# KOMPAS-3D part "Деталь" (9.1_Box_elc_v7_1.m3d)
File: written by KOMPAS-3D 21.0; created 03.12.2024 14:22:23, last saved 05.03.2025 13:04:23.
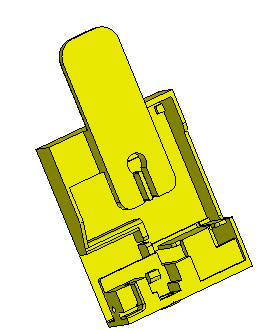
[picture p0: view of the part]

Document properties: Автор: Admin; Полное имя файла: Z:\!_Силкин\!!!_Дрон\Autel Robotics EVO Lite\Подвес\EVO\V7\9.1_Box_elc_v7_1.m3d

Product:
- Part/product: Деталь
    Масса: 0.062518

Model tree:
1. Эскиз:1
2. Элемент выдавливания:1
     Расстояние 1 = 41
3. Эскиз:2  (with: Элемент выдавливания:1)
4. Элемент выдавливания:2
     Расстояние 1 = 1
5. Эскиз:3  (with: Элемент выдавливания:1)
6. Элемент выдавливания:3
     Расстояние 1 = 1
7. Эскиз:4  (with: Элемент выдавливания:1, Элемент выдавливания:3)
8. Элемент выдавливания:4
     Расстояние 2 = 38
9. Фаска:1  (with: Элемент выдавливания:1, Элемент выдавливания:3)
     Угол = 45; Длина 1 = 1; Длина 2 = 1
10. Эскиз:5  (with: Элемент выдавливания:2)
11. Элемент выдавливания:5
     Расстояние 2 = 10
12. Эскиз:6  (with: Элемент выдавливания:2)
13. Элемент выдавливания:6
     Расстояние 2 = 10
14. Эскиз:7  (with: Элемент выдавливания:1)
15. Элемент выдавливания:7
     Расстояние 1 = 12
16. Эскиз:8  (with: Элемент выдавливания:1, Элемент выдавливания:5, Элемент выдавливания:7)
17. Эскиз:9  (with: Элемент выдавливания:1, Элемент выдавливания:3)
18. Элемент выдавливания:8
     Расстояние 1 = 3
19. Эскиз:10  (with: Элемент выдавливания:7, Элемент выдавливания:4)
20. Элемент выдавливания:9
     Расстояние 1 = 1
21. Эскиз:11  (with: Элемент выдавливания:1, Элемент выдавливания:3, Элемент выдавливания:8)
22. Элемент выдавливания:10
     Расстояние 1 = 1
23. Эскиз:12  (with: Элемент выдавливания:8, Элемент выдавливания:10)
24. Элемент выдавливания:11
     Расстояние 1 = 1; Расстояние 2 = 1
25. Эскиз:13  (with: Элемент выдавливания:2, Элемент выдавливания:5)
26. Эскиз:14  (with: Элемент выдавливания:1, Элемент выдавливания:8)
27. Элемент выдавливания:12
     Расстояние 1 = 3.5
28. Эскиз:15  (with: Элемент выдавливания:2, Элемент выдавливания:5)
29. Элемент выдавливания:13
     Расстояние 2 = 3.5
30. Эскиз:16  (with: Элемент выдавливания:12)
31. Элемент выдавливания:14
     Расстояние 2 = 4
32. Элемент выдавливания:16  (with: Элемент выдавливания:2, Элемент выдавливания:12)
     Расстояние 1 = 3.5
33. Фаска:3  (with: Элемент выдавливания:4)
     Угол = 45; Длина 1 = 1; Длина 2 = 1
34. Эскиз:18  (with: Элемент выдавливания:2, Элемент выдавливания:7, Элемент выдавливания:14)
35. Элемент выдавливания:17
     Расстояние 1 = 4
36. Эскиз:19  (with: Элемент выдавливания:7, Элемент выдавливания:17)
37. Элемент выдавливания:18
     Расстояние 1 = 10
38. Эскиз:20  (with: Элемент выдавливания:13, Элемент выдавливания:18)
39. Элемент выдавливания:19  (with: Элемент выдавливания:7)
     Расстояние 1 = 4
40. Эскиз:21  (with: Элемент выдавливания:17)
41. Элемент выдавливания:20
     Расстояние 2 = 10
42. Эскиз:22  (with: Элемент выдавливания:2, Фаска:1, Элемент выдавливания:6, Элемент выдавливания:14, Элемент выдавливания:20)
43. Элемент выдавливания:21
     Расстояние 1 = 3.5
44. Эскиз:23  (with: Элемент выдавливания:1, Элемент выдавливания:17)
45. Элемент выдавливания:22
     Расстояние 2 = 3.5
46. Эскиз:24  (with: Элемент выдавливания:7, Элемент выдавливания:17, Элемент выдавливания:18)
47. Элемент выдавливания:23
     Расстояние 2 = 4
48. Эскиз:25  (with: Элемент выдавливания:7, Элемент выдавливания:17, Элемент выдавливания:23)
49. Элемент выдавливания:24
     Расстояние 2 = 7
50. Эскиз:26  (with: Элемент выдавливания:7, Элемент выдавливания:23, Элемент выдавливания:24)
51. Элемент выдавливания:25  (with: Элемент выдавливания:1)
     Расстояние 1 = 1.4
52. Эскиз:27  (with: Элемент выдавливания:24, Элемент выдавливания:25)
53. Элемент выдавливания:26  (with: Элемент выдавливания:12)
     Расстояние 1 = -1.5
54. Эскиз:28  (with: Элемент выдавливания:26, Элемент выдавливания:24)
55. Элемент выдавливания:27
     Расстояние 2 = 10
56. Эскиз:29
57. Элемент выдавливания:28
     Расстояние 1 = 12
58. Эскиз:30  (with: Элемент выдавливания:4, Элемент выдавливания:28, Фаска:1)
59. Элемент выдавливания:29
     Расстояние 1 = 13
60. Элемент выдавливания:30  (with: Элемент выдавливания:4)
     Расстояние 1 = 1.4
61. Эскиз:31  (with: Элемент выдавливания:4, Фаска:1)
62. Элемент выдавливания:31  (with: Элемент выдавливания:1)
     Расстояние 1 = -9
63. Эскиз:32  (with: Элемент выдавливания:4)
64. Элемент выдавливания:32  (with: Элемент выдавливания:1)
     Расстояние 2 = 8
65. Эскиз:33  (with: Элемент выдавливания:11)
66. Элемент выдавливания:34  (with: Элемент выдавливания:1)
     Расстояние 2 = 3.5
67. Эскиз:34  (with: Элемент выдавливания:1, Элемент выдавливания:10, Элемент выдавливания:34)
68. Элемент выдавливания:35
     Расстояние 1 = 10
69. Элемент выдавливания:36  (with: Элемент выдавливания:8, Элемент выдавливания:4)
     Расстояние 1 = 5
70. Эскиз:35  (with: Элемент выдавливания:1, Элемент выдавливания:4)
71. Элемент выдавливания:37
72. Эскиз:36  (with: Элемент выдавливания:12, Элемент выдавливания:27)
73. Элемент выдавливания:38
     Расстояние 1 = 1
74. Скругление:1  (with: Элемент выдавливания:38)
     Радиус = 0.5
75. Скругление:2  (with: Элемент выдавливания:38)
     Радиус = 0.5
76. Эскиз:37  (with: Элемент выдавливания:28)
77. Элемент выдавливания:40  (with: Элемент выдавливания:8)
     Расстояние 1 = 5.7; Расстояние 2 = 12
78. Эскиз:38  (with: Элемент выдавливания:28, Элемент выдавливания:37)
79. Элемент выдавливания:41
     Расстояние 2 = 10
80. Фаска:4  (with: Элемент выдавливания:1, Элемент выдавливания:31)
     Угол = 45; Длина 1 = 1; Длина 2 = 1
81. Элемент выдавливания:42  (with: Элемент выдавливания:17)
     Расстояние 1 = 1
82. Скругление:3  (with: Элемент выдавливания:36, Элемент выдавливания:35)
     Радиус = 1
83. Элемент выдавливания:43  (with: Элемент выдавливания:12)
     Расстояние 1 = 0.4
84. Фаска:5  (with: Элемент выдавливания:13)
     Угол = 45; Длина 1 = 0.5; Длина 2 = 0.5
85. Элемент выдавливания:44  (with: Элемент выдавливания:7)
     Расстояние 1 = 2
86. Эскиз:39  (with: Элемент выдавливания:43, Фаска:1)
87. Элемент выдавливания:45
     Расстояние 2 = 8
88. Эскиз:40  (with: Элемент выдавливания:43)
89. Элемент выдавливания:46
     Расстояние 2 = 10
90. Элемент выдавливания:48  (with: Элемент выдавливания:28)
     Расстояние 1 = 1
91. Фаска:6  (with: Элемент выдавливания:7)
     Угол = 45; Длина 1 = 2; Длина 2 = 2
92. Эскиз:41
93. Элемент выдавливания:49
     Расстояние 2 = 9
94. Эскиз:43  (with: Элемент выдавливания:25, Элемент выдавливания:43)
95. Элемент выдавливания:51
     Расстояние 2 = 10
96. Эскиз:44  (with: Элемент выдавливания:49)
97. Элемент выдавливания:52
     Расстояние 2 = 2
98. Эскиз:45  (with: Элемент выдавливания:25)
99. Элемент выдавливания:53
     Расстояние 2 = 2
100. Элемент выдавливания:54  (with: Элемент выдавливания:2)
     Расстояние 1 = 3
101. Эскиз:46  (with: Элемент выдавливания:25, Элемент выдавливания:54)
102. Элемент выдавливания:56
     Расстояние 2 = 2
103. Эскиз:47  (with: Элемент выдавливания:54, Элемент выдавливания:56)
104. Элемент выдавливания:57  (with: Элемент выдавливания:7)
     Расстояние 1 = 1
105. Эскиз:48  (with: Элемент выдавливания:43)
106. Элемент выдавливания:58
     Расстояние 2 = 10
107. Эскиз:49  (with: Элемент выдавливания:1, Фаска:5)
108. Эскиз:50  (with: Элемент выдавливания:13, Элемент выдавливания:54, Элемент выдавливания:58)
109. Элемент выдавливания:59  (with: Элемент выдавливания:1)
     Расстояние 2 = 1
110. Фаска:7  (with: Элемент выдавливания:59)
     Угол = 45; Длина 1 = 0.5; Длина 2 = 0.5
111. Эскиз:51  (with: Элемент выдавливания:43)
112. Элемент выдавливания:60  (with: Элемент выдавливания:13)
     Расстояние 2 = 1.4
113. Фаска:8  (with: Элемент выдавливания:60)
     Угол = 45; Длина 1 = 0.5; Длина 2 = 0.5
114. Эскиз:52  (with: Элемент выдавливания:13, Элемент выдавливания:22)
115. Элемент выдавливания:61  (with: Элемент выдавливания:7)
     Расстояние 1 = 7.5
116. Эскиз:53  (with: Элемент выдавливания:26, Элемент выдавливания:27)
117. Элемент выдавливания:62
     Расстояние 2 = 10
118. Скругление:4  (with: Элемент выдавливания:49)
     Радиус = 0.5
119. Элемент выдавливания:63  (with: Элемент выдавливания:53)
     Расстояние 2 = 2
120. Эскиз:54  (with: Элемент выдавливания:7, Элемент выдавливания:61, Элемент выдавливания:63)
121. Элемент выдавливания:64  (with: Элемент выдавливания:43)
     Расстояние 2 = 8.9
122. Элемент выдавливания:65  (with: Элемент выдавливания:61)
     Расстояние 1 = 1
123. Элемент выдавливания:66  (with: Элемент выдавливания:63, Элемент выдавливания:25)
     Расстояние 1 = 4
124. Эскиз:55  (with: Элемент выдавливания:25, Элемент выдавливания:41, Элемент выдавливания:64, Элемент выдавливания:22)
125. Элемент выдавливания:67
     Расстояние 2 = 10
126. Эскиз:56  (with: Элемент выдавливания:1, Элемент выдавливания:28)
127. Элемент выдавливания:68
     Расстояние 2 = 10
128. Эскиз:57  (with: Элемент выдавливания:1)
129. Элемент выдавливания:69
     Расстояние 2 = 10
130. Элемент выдавливания:71  (with: Элемент выдавливания:28, Элемент выдавливания:40)
     Расстояние 1 = 5.7
131. Эскиз:58  (with: Элемент выдавливания:1, Элемент выдавливания:68, Элемент выдавливания:22, Элемент выдавливания:61)
132. Элемент выдавливания:72
133. Эскиз:60  (with: Элемент выдавливания:43)
134. Элемент выдавливания:74
     Расстояние 2 = 5
135. Эскиз:61  (with: Элемент выдавливания:43)
136. Элемент выдавливания:75
     Расстояние 1 = 10
137. Скругление:5  (with: Элемент выдавливания:74)
     Радиус = 0.5
138. Элемент выдавливания:76
     Расстояние 2 = 10
139. Элемент выдавливания:77  (with: Элемент выдавливания:28)
     Расстояние 1 = 1
140. Эскиз:62  (with: Элемент выдавливания:43, Элемент выдавливания:46)
141. Элемент выдавливания:78
     Расстояние 2 = 1.4
142. Эскиз:63  (with: Элемент выдавливания:43, Элемент выдавливания:78, Элемент выдавливания:72)
143. Элемент выдавливания:79
     Расстояние 2 = 10
144. Эскиз:64  (with: Элемент выдавливания:1, Элемент выдавливания:40, Элемент выдавливания:79)
145. Элемент выдавливания:80  (with: Элемент выдавливания:72)
     Расстояние 1 = 4.8
146. Эскиз:65  (with: Элемент выдавливания:67)
147. Элемент выдавливания:81  (with: Элемент выдавливания:80)
     Расстояние 2 = 16.1
148. Скругление:6  (with: Элемент выдавливания:78, Элемент выдавливания:79)
     Радиус = 1
149. Эскиз:66  (with: Элемент выдавливания:81)
150. Элемент выдавливания:82
     Расстояние 2 = 16.1
151. Эскиз:67  (with: Элемент выдавливания:1, Элемент выдавливания:32, Элемент выдавливания:81)
152. Элемент выдавливания:83
     Расстояние 1 = 10
153. Эскиз:68  (with: Элемент выдавливания:1, Элемент выдавливания:4, Фаска:1, Элемент выдавливания:81)
154. Элемент выдавливания:84
     Расстояние 2 = 1
155. Эскиз:69  (with: Элемент выдавливания:1, Элемент выдавливания:32, Элемент выдавливания:80)
156. Элемент выдавливания:85
     Расстояние 1 = 5
157. Эскиз:70  (with: Элемент выдавливания:32)
158. Элемент выдавливания:86
     Расстояние 1 = 10
159. Эскиз:71  (with: Элемент выдавливания:80, Элемент выдавливания:82)
160. Элемент выдавливания:87
     Расстояние 1 = 10
161. Эскиз:72  (with: Элемент выдавливания:81, Фаска:1, Элемент выдавливания:82)
162. Элемент выдавливания:89
     Расстояние 2 = 16.1
163. Элемент выдавливания:90  (with: Элемент выдавливания:43)
     Расстояние 1 = 0.2
164. Элемент выдавливания:91  (with: Элемент выдавливания:69)
     Расстояние 1 = 0.2
165. Эскиз:73  (with: Элемент выдавливания:80, Элемент выдавливания:10)
166. Элемент выдавливания:92  (with: Элемент выдавливания:4, Элемент выдавливания:1)
     Расстояние 1 = 3.2; Расстояние 2 = 4.8
167. Эскиз:74  (with: Элемент выдавливания:80, Элемент выдавливания:81, Элемент выдавливания:92)
168. Элемент выдавливания:93
     Расстояние 2 = 4.8
169. Элемент выдавливания:94  (with: Элемент выдавливания:85, Элемент выдавливания:4)
     Расстояние 1 = 3
170. Эскиз:75  (with: Элемент выдавливания:24, Элемент выдавливания:23, Фаска:6)
171. Элемент выдавливания:95
     Расстояние 2 = 0.6
172. Эскиз:76  (with: Элемент выдавливания:24, Элемент выдавливания:25)
173. Элемент выдавливания:96  (with: Элемент выдавливания:80)
     Расстояние 2 = 1.04101
174. Элемент выдавливания:97
     Расстояние 1 = 1.15585
175. Эскиз:77  (with: Элемент выдавливания:80, Элемент выдавливания:92)
176. Элемент выдавливания:98  (with: Элемент выдавливания:1)
     Расстояние 2 = 4.8
177. Эскиз:78  (with: Элемент выдавливания:80, Элемент выдавливания:82, Элемент выдавливания:92)
178. Элемент выдавливания:99  (with: Элемент выдавливания:82)
     Расстояние 2 = 1.8
179. Эскиз:79  (with: Элемент выдавливания:4)
180. Элемент выдавливания:101
     Расстояние 1 = 4.3
181. Эскиз:80  (with: Элемент выдавливания:86, Элемент выдавливания:93, Элемент выдавливания:101)
182. Элемент выдавливания:102  (with: Элемент выдавливания:101)
     Расстояние 1 = 11.2968
183. Эскиз:81  (with: Элемент выдавливания:1, Элемент выдавливания:25, Элемент выдавливания:32)
184. Элемент выдавливания:103
     Расстояние 2 = 2
185. Скругление:7  (with: Элемент выдавливания:103)
     Радиус = 1
186. Скругление:8  (with: Элемент выдавливания:103)
     Радиус = 1
187. Эскиз:82  (with: Элемент выдавливания:101)
188. Элемент выдавливания:104
     Расстояние 2 = 3.2
189. Скругление:9  (with: Элемент выдавливания:102)
     Радиус = 1
190. Скругление:10  (with: Элемент выдавливания:101)
     Радиус = 1
191. Элемент выдавливания:105  (with: Элемент выдавливания:96, Элемент выдавливания:7)
     Расстояние 1 = 2.09062
192. Эскиз:83  (with: Элемент выдавливания:72, Элемент выдавливания:42)
193. Элемент выдавливания:106  (with: Элемент выдавливания:24)
     Расстояние 2 = 10.6
194. Эскиз:86  (with: Элемент выдавливания:82, Элемент выдавливания:106)
195. Элемент выдавливания:109
     Расстояние 1 = 10
196. Элемент выдавливания:110  (with: Элемент выдавливания:99, Элемент выдавливания:1)
     Расстояние 2 = 3
197. Эскиз:87  (with: Элемент выдавливания:81, Элемент выдавливания:82, Элемент выдавливания:89, Элемент выдавливания:110)
198. Элемент выдавливания:111
     Расстояние 2 = 16.1
199. Эскиз:88  (with: Элемент выдавливания:7, Элемент выдавливания:17, Элемент выдавливания:24, Элемент выдавливания:25, Элемент выдавливания:105, Элемент выдавливания:62)
200. Элемент выдавливания:112  (with: Элемент выдавливания:95)
     Расстояние 2 = 3.64745
201. Элемент выдавливания:113  (with: Элемент выдавливания:95, Элемент выдавливания:24)
     Расстояние 1 = 0.6
202. Эскиз:89  (with: Элемент выдавливания:112, Элемент выдавливания:105, Элемент выдавливания:90, Элемент выдавливания:38)
203. Элемент выдавливания:114
     Расстояние 1 = 2
204. Скругление:11  (with: Элемент выдавливания:114)
     Радиус = 1
205. Эскиз:90  (with: Элемент выдавливания:104)
206. Элемент выдавливания:115
     Расстояние 1 = 1
207. Скругление:12  (with: Элемент выдавливания:115)
     Радиус = 0.2
208. Скругление:13  (with: Элемент выдавливания:104)
     Радиус = 0.5
209. Эскиз:97  (with: Элемент выдавливания:7, Элемент выдавливания:105, Элемент выдавливания:31)
210. Элемент выдавливания:117
     Расстояние 2 = 4
211. Эскиз:99  (with: Элемент выдавливания:7)
212. Элемент выдавливания:119
     Расстояние 2 = 2.6
213. Скругление:15  (with: Элемент выдавливания:119)
     Радиус = 1
214. Элемент выдавливания:120  (with: Элемент выдавливания:112)
     Расстояние 2 = 5.25
215. Эскиз:100  (with: Элемент выдавливания:25, Элемент выдавливания:90)
216. Элемент выдавливания:121
     Расстояние 2 = 3.5
217. Скругление:16  (with: Элемент выдавливания:121)
     Радиус = 0.5
218. Эскиз:101  (with: Элемент выдавливания:35)
219. Элемент выдавливания:122
     Расстояние 1 = 2; Расстояние 2 = 2
220. Скругление:17  (with: Элемент выдавливания:122)
     Радиус = 1
221. Скругление:18  (with: Элемент выдавливания:82, Элемент выдавливания:99)
     Радиус = 1
222. Скругление:19  (with: Элемент выдавливания:86)
     Радиус = 1
223. Эскиз:102  (with: Элемент выдавливания:25, Элемент выдавливания:112)
224. Элемент выдавливания:123  (with: Элемент выдавливания:112)
     Расстояние 2 = 6.55899
225. Эскиз:103  (with: Элемент выдавливания:1, Элемент выдавливания:31, Фаска:1, Элемент выдавливания:4)
226. Элемент выдавливания:124  (with: Элемент выдавливания:1)
     Расстояние 2 = 1
227. Эскиз:104  (with: Элемент выдавливания:101, Элемент выдавливания:102)
228. Элемент выдавливания:125
     Расстояние 2 = 14
229. Эскиз:105  (with: Элемент выдавливания:81, Элемент выдавливания:89)
230. Элемент выдавливания:126
     Расстояние 2 = 16.1
231. Эскиз:106  (with: Элемент выдавливания:72, Элемент выдавливания:90, Элемент выдавливания:112)
232. Элемент выдавливания:127
     Расстояние 2 = 17.7
233. Эскиз:108  (with: Элемент выдавливания:112)
234. Скругление:20  (with: Элемент выдавливания:127)
     Радиус = 0.5
235. Скругление:21  (with: Элемент выдавливания:126)
     Радиус = 1
236. Элемент выдавливания:128  (with: Элемент выдавливания:8, Элемент выдавливания:10)
     Расстояние 1 = 7.05
237. Элемент выдавливания:129  (with: Элемент выдавливания:81)
     Расстояние 1 = 1
238. Скругление:22  (with: Элемент выдавливания:129)
     Радиус = 1
239. Скругление:23  (with: Элемент выдавливания:101)
     Радиус = 1
240. Эскиз:109  (with: Элемент выдавливания:56)
241. Элемент выдавливания:130  (with: Элемент выдавливания:56)
     Расстояние 1 = 0.4
242. Элемент выдавливания:131  (with: Элемент выдавливания:130, Элемент выдавливания:5)
     Расстояние 1 = 1
243. Эскиз:110  (with: Элемент выдавливания:90)
244. Элемент выдавливания:132
     Расстояние 2 = 12.6
245. Элемент выдавливания:133  (with: Элемент выдавливания:56)
     Расстояние 1 = 1
246. Элемент выдавливания:134  (with: Элемент выдавливания:5, Элемент выдавливания:132)
     Расстояние 2 = 0.5
247. Элемент выдавливания:135  (with: Элемент выдавливания:132)
     Расстояние 2 = 0.5
248. Скругление:24  (with: Элемент выдавливания:132)
     Радиус = 0.5
249. Эскиз:111  (with: Элемент выдавливания:25, Скругление:16)
250. Элемент выдавливания:136  (with: Элемент выдавливания:121)
     Расстояние 2 = 3.5
251. Эскиз:112  (with: Элемент выдавливания:101, Элемент выдавливания:104, Элемент выдавливания:74)
252. Элемент выдавливания:137
     Расстояние 2 = 2.1
253. Эскиз:113  (with: Элемент выдавливания:4, Элемент выдавливания:31, Элемент выдавливания:32, Элемент выдавливания:86, Элемент выдавливания:92, Элемент выдавливания:101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)
254. Элемент выдавливания:138  (with: Элемент выдавливания:137)
     Расстояние 1 = 2.2
255. Скругление:26  (with: Элемент выдавливания:137)
     Радиус = 0.6
256. Элемент выдавливания:139  (with: Элемент выдавливания:101)
     Расстояние 1 = 0.2
257. Эскиз:114  (with: Элемент выдавливания:81, Элемент выдавливания:89, Элемент выдавливания:41)
258. Элемент выдавливания:140  (with: Элемент выдавливания:80)
     Расстояние 2 = 16.1
259. Эскиз:115  (with: Элемент выдавливания:101, Элемент выдавливания:125)
260. Элемент выдавливания:141  (with: Элемент выдавливания:32)
261. Элемент выдавливания:142  (with: Элемент выдавливания:101, Элемент выдавливания:125)
     Расстояние 2 = 0.329173
262. Элемент выдавливания:143  (with: Элемент выдавливания:141)
     Расстояние 2 = 4

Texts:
  Точка начала. Х
  Точка начала. Y
  Точка начала. Z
